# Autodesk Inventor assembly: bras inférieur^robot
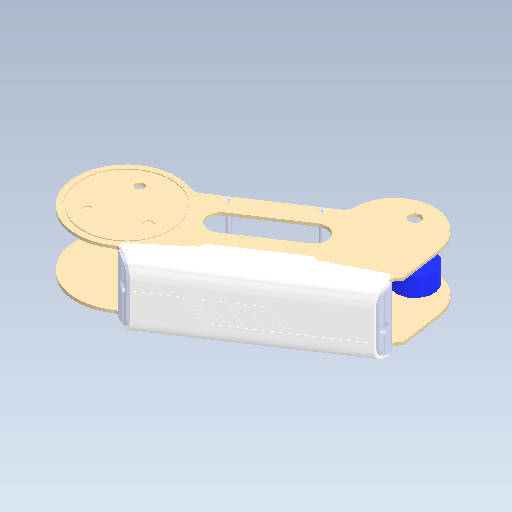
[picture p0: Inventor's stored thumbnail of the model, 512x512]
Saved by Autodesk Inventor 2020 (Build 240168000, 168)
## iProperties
Created: 2018-10
Part Number: bras inférieur^robot
Document SubType Name: Assembly
Designer: bruno
Sending System: SolidWorks 2016
Last Author: Prof
Last Saved: 2018-10-03
Author: bruno
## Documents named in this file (12)
- C:\Users\bruno\Documents\Systèmes\Mallette Bras robotisé (273265)\Dossier ressources\Maquette Dobot SW2016\bras inférieur^robot.iam
- C:\Users\bruno\Documents\Systèmes\Mallette Bras robotisé (273265)\Dossier ressources\Maquette Dobot SW2016\MSCS0403_A.ipt
- C:\Users\bruno\Documents\Systèmes\Mallette Bras robotisé (273265)\Dossier ressources\Maquette Dobot SW2016\_____M2_5_A.ipt
- C:\Users\bruno\Documents\Systèmes\Mallette Bras robotisé (273265)\Dossier ressources\Maquette Dobot SW2016\_____28_A.ipt
- C:\Users\bruno\Documents\Systèmes\Mallette Bras robotisé (273265)\Dossier ressources\Maquette Dobot SW2016\______27_A.ipt
- C:\Users\bruno\Documents\Systèmes\Mallette Bras robotisé (273265)\Dossier ressources\Maquette Dobot SW2016\_______26_A.ipt
- C:\Users\bruno\Documents\Systèmes\Mallette Bras robotisé (273265)\Dossier ressources\Maquette Dobot SW2016\_______25_A.ipt
- C:\Users\bruno\Documents\Systèmes\Mallette Bras robotisé (273265)\Dossier ressources\Maquette Dobot SW2016\_______24_A.ipt
- C:\Users\bruno\Documents\Systèmes\Mallette Bras robotisé (273265)\Dossier ressources\Maquette Dobot SW2016\_______23_A.ipt
- C:\Users\bruno\Documents\Systèmes\Mallette Bras robotisé (273265)\Dossier ressources\Maquette Dobot SW2016\BREP_3-965.ipt
- C:\Users\bruno\Documents\Systèmes\Mallette Bras robotisé (273265)\Dossier ressources\Maquette Dobot SW2016\____230_A.ipt
- C:\Users\bruno\Documents\Systèmes\Mallette Bras robotisé (273265)\Dossier ressources\Maquette Dobot SW2016\____21_A.ipt
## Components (16 placed, 11 different names)
1. MSCS0403_A:1
2. _____M2_5_A:1
3. _____M2_5_A:2
4. _____M2_5_A:3
5. _____M2_5_A:4
6. _____28_A:1
7. _____28_A:2
8. ______27_A:1
9. _______26_A:1
10. _______25_A:1
11. _______24_A:1
12. _______23_A:1
13. BREP_3-965:1
14. ____230_A:1
15. ____21_A:1
16. ____21_A:2
